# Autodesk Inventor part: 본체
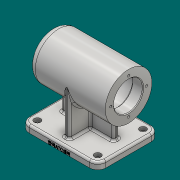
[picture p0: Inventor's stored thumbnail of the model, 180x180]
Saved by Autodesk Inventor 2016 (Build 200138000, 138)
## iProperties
Created: 2020-10
Part Number: 본체
Material: 알루미늄 6061
Document SubType Name: Modeling
Designer: 605-12
Density: 2.7 g/cm^3
Appearance: 알루미늄 - 평지
Mass: 1026.28 g
Surface Area: 757.984 cm^2
Volume: 380.103 cm^3
Author: 605-12
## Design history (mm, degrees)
sketch "스케치1"
  geometry: L1 (-56, 45)-(56, 45); L2 (56, 45)-(56, -45); L3 (56, -45)-(-56, -45); L4 (-56, -45)-(-56, 45); L5 (-56, 45)-(56, -45); L6 (56, 45)-(-56, -45); 1 further point
  constraints: 12 end point, 2 midpoint, 2 parallel, 1 horizontal, 1 perpendicular
  dimensions: "d0" = 90 distance of L1.end L2.end; "d1" = 112 distance of L1.start L1.end
extrude "돌출1" new body sketch "스케치1" distance "d2" = 10; taper "d3" = 0 deg
sketch "스케치2"
  geometry: L1 (56, 74)-(-56, 74); L2 (56, 0)-(-56, 0) reference; L3 (56, 74)-(56, 108); L4 (56, 108)-(-56, 108); L5 (-56, 108)-(-56, 74); L6 (50, 74)-(50, 84.5); L7 (50, 84.5)-(47, 84.5); L8 (47, 84.5)-(47, 90); L9 (47, 90)-(43, 90); L10 (43, 90)-(43, 91.5); L11 (43, 91.5)-(25, 91.5); L12 (25, 91.5)-(25, 95); L13 (25, 95)-(13, 95); L14 (13, 95)-(13, 98); L15 (13, 98)-(-41, 98); L16 (-41, 98)-(-41, 95); L17 (-41, 95)-(-56, 95); 3 further points
  constraints: 32 end point, 13 perpendicular, 2 midpoint, 2 point on line, 2 vertical, 1 horizontal, 1 vertical alignment
  dimensions: "d4" = 74 distance from line of L2 L1.start; "d5" = 21 diameter of L7 L1; "d6" = 32 diameter of L9 L1; "d7" = 35 diameter of L11 L1; "d8" = 42 diameter of L13 L1; "d9" = 48 diameter of L15 L1; "d10" = 42 diameter of L17 L1; "d11" = 68 diameter of L4 L1; "d12" = 3 distance of L6.end L7.end; "d13" = 4 distance of L8.end L9.end; "d14" = 18 distance of L10.end L11.end; "d15" = 12 distance of L12.end L13.end; "d16" = 54 distance of L14.end L15.end; "d17" = 15 distance of L16.end L17.end; "d18" = 112 distance of L3.end L4.end
revolve "회전1" sketch "스케치2" stored, may be unused: angle "d19" = 90 deg
sketch "스케치3"
  geometry: L1 (-38, 4)-(38, 4); L2 (38, 4)-(38, -4); L3 (38, -4)-(-38, -4); L4 (-38, -4)-(-38, 4); L5 (-38, 4)-(38, -4); L6 (38, 4)-(-38, -4); L7 (-4, 34)-(4, 34); L8 (4, 34)-(4, -34); L9 (4, -34)-(-4, -34); L10 (-4, -34)-(-4, 34); L11 (-4, 34)-(4, -34); L12 (4, 34)-(-4, -34); L13 (-56, -45)-(-56, 45) reference; 1 further point
  constraints: 24 end point, 4 midpoint, 4 parallel, 2 horizontal, 2 perpendicular
  dimensions: "d20" = 8 distance of L7.start L7.end; "d21" = 8 distance of L1.end L2.end; "d22" = 18 distance between parallel lines of L13 L4; "d23" = 68 distance of L7.end L8.end
extrude "돌출2" join sketch "스케치3" stored distance "d24" = 10; taper "d25" = 0 deg
fillet "모깎기1" dims "d26" = 0.3
fillet "모깎기2" dims "d27" = 3
chamfer "모따기1" distance "d28" = 1; stored, may be unused: second distance "d29" = 2, angle "d30" = 45 deg
fillet "모깎기3" dims "d31" = 10
fillet "모깎기4" dims "d32" = 3
fillet "모깎기5" dims "d33" = 12
fillet "모깎기6" dims "d34" = 3
sketch "스케치4"
  geometry: L1 (0, 0)-(-26, 0); C1 r 34 at (0, 0) reference; 1 further point
  constraints: 2 end point, 1 horizontal
  dimensions: "d35" = 26 distance of L1.start L1.end
hole "구멍1" sketch "스케치4" at (-26, 0) diameter "d36" = 3.242; stored, may be unused: countersink angle "d40" = 90 deg, drill point angle "d42" = 118 deg; dims "d37" = 8, "d38" = 4, "d39" = 2, "d41" = 11
sketch "스케치5"
  geometry: L1 (-56, -33)-(-56, 33) reference; L2 (-44, 45)-(44, 45) reference; L3 (56, 33)-(56, -33) reference; L4 (44, -45)-(-44, -45) reference; A1 r 12 centre (-44, -33) between (-56, -33) and (-44, -45) reference; A2 r 12 centre (-44, 33) between (-44, 45) and (-56, 33) reference; A3 r 12 centre (44, 33) between (56, 33) and (44, 45) reference; A4 r 12 centre (44, -33) between (44, -45) and (56, -33) reference; 1 further point
hole "구멍2" sketch "스케치5" at (-44, 33), (44, 33), (44, -33), (-44, -33) diameter "d46" = 5.5; stored, may be unused: countersink angle "d50" = 90 deg, drill point angle "d52" = 118 deg; dims "d47" = 8, "d48" = 9.5, "d49" = 5.4, "d51" = 11
sketch "스케치6"
  geometry: L1 (100, 0)-(100, 7) reference; 2 further points
  constraints: 1 other
  dimensions: "d53" = 56 distance from line of L1 point (44, 3); "d54" = 3 vertical distance of point (44, 3) L1.start
feature "엠보싱1" sketch "스케치6" dims "d55" = 0.5, "d56" = 0
node "솔리드1"
pattern_circular "원형 패턴1" dims angle "d44" = 360 deg
node "투영된 루프1"
